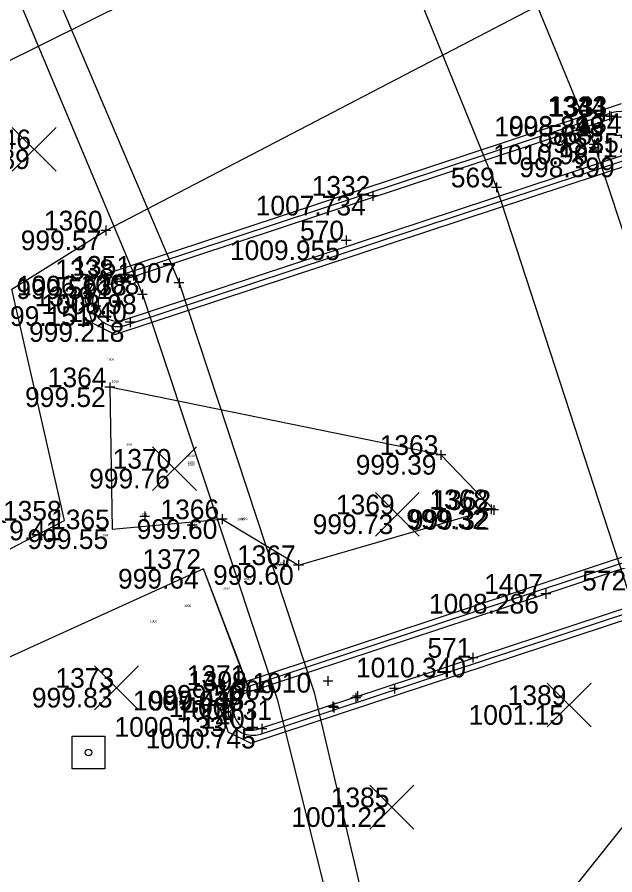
# Model space of a CAD drawing. Extents: x 2354693 to 2355622, y 637071 to 710080.
# Drawn here: x 2355324.2 to 2355360.6, y 709282.3 to 709334.6 of the extents above; entities that cross this region are included whole.
import ezdxf

# ---------------------------------------------------------------- set-up
doc = ezdxf.new("R2010")
doc.units = 0
for name, color, linetype in [('BR_X_Sub_Foot_Object', 7, 'Continuous'), ('BR_X_SV_Beam_Seat', 7, 'Continuous'), ('BR_X_SV_Pier', 7, 'Continuous'), ('BR_X_SV_Pier_Text', 7, 'Continuous'), ('DT_X_Spot_Elev', 7, 'Continuous'), ('HY_X_Water_Edge', 7, 'Continuous'), ('PM_X_Surveyed_Line', 7, 'Continuous'), ('PV_X_EOP', 7, 'Continuous'), ('SV_X_Control_Cells_Found', 7, 'Continuous'), ('SV_X_Random_Point', 7, 'Continuous'), ('SV_X_Shot_Marker', 7, 'Continuous'), ('SV_X_Text_Elevation', 7, 'Continuous'), ('SV_X_Text_Name', 7, 'Continuous'), ('SV_X_Toe_of_Slope', 7, 'Continuous')]:
    doc.layers.add(name, color=color, linetype=linetype)

msp = doc.modelspace()

# ---------------------------------------------------------------- linework, layer by layer
at = {"layer": 'BR_X_Sub_Foot_Object'}
for p, q in [((2355328.996, 709318.714), (2355360.982, 709329.286)), ((2355330.146, 709315.233), (2355362.132, 709325.804)), ((2355328.996, 709318.714), (2355328.314, 709317.359)), ((2355328.314, 709317.359), (2355328.791, 709315.915)), ((2355330.146, 709315.233), (2355328.791, 709315.915)), ((2355337.246, 709293.829), (2355369.232, 709304.4)), ((2355338.397, 709290.347), (2355370.383, 709300.918)), ((2355337.246, 709293.829), (2355336.564, 709292.473)), ((2355336.564, 709292.473), (2355337.042, 709291.029)), ((2355338.397, 709290.347), (2355337.042, 709291.029))]:
    msp.add_line(p, q, dxfattribs=at)
at = {"layer": 'BR_X_SV_Beam_Seat'}
for p, q in [((2355360.639, 709328.496), (2355360.039, 709328.496)), ((2355360.339, 709328.796), (2355360.339, 709328.196)), ((2355345.85, 709323.978), (2355345.85, 709323.378)), ((2355346.15, 709323.678), (2355345.55, 709323.678)), ((2355331.289, 709319.11), (2355331.289, 709318.51)), ((2355331.589, 709318.81), (2355330.989, 709318.81)), ((2355356.366, 709299.742), (2355356.366, 709299.142)), ((2355356.666, 709299.442), (2355356.066, 709299.442)), ((2355338.656, 709293.543), (2355338.056, 709293.543)), ((2355338.356, 709293.843), (2355338.356, 709293.243))]:
    msp.add_line(p, q, dxfattribs=at)
at = {"layer": 'BR_X_SV_Pier'}
for p, q in [((2355329.927, 709318.32), (2355360.469, 709328.414)), ((2355329.991, 709318.692), (2355360.276, 709328.701)), ((2355330.659, 709316.105), (2355361.201, 709326.199)), ((2355330.764, 709315.788), (2355361.306, 709325.882)), ((2355338.178, 709293.434), (2355368.719, 709303.528)), ((2355338.241, 709293.806), (2355368.526, 709303.816)), ((2355338.91, 709291.219), (2355369.452, 709301.313)), ((2355339.014, 709290.902), (2355369.556, 709300.996))]:
    msp.add_line(p, q, dxfattribs=at)
for centre, radius, start, end in [((2355360.835, 709327.306), 1.5, 288.2885, 108.2885), ((2355360.835, 709327.306), 1.167, 288.2885, 108.2885), ((2355330.293, 709317.212), 1.5, 108.2885, 288.2885), ((2355330.293, 709317.212), 1.167, 108.2885, 288.2885), ((2355338.544, 709292.327), 1.5, 108.2885, 288.2885), ((2355338.544, 709292.327), 1.167, 108.2885, 288.2885)]:
    msp.add_arc(centre, radius, start, end, dxfattribs=at)
at = {"layer": 'BR_X_SV_Pier_Text'}
for p, q in [((2355360.537, 709328.523), (2355359.937, 709328.523)), ((2355360.554, 709328.532), (2355359.954, 709328.532)), ((2355360.554, 709328.532), (2355359.954, 709328.532)), ((2355360.237, 709328.823), (2355360.237, 709328.223)), ((2355360.254, 709328.832), (2355360.254, 709328.232)), ((2355360.254, 709328.832), (2355360.254, 709328.232)), ((2355330.578, 709318.594), (2355329.978, 709318.594)), ((2355330.278, 709318.894), (2355330.278, 709318.294)), ((2355329.298, 709316.954), (2355328.698, 709316.954)), ((2355328.998, 709317.254), (2355328.998, 709316.654)), ((2355331.376, 709315.986), (2355330.776, 709315.986)), ((2355331.076, 709316.286), (2355331.076, 709315.686)), ((2355338.641, 709293.54), (2355338.041, 709293.54)), ((2355338.341, 709293.84), (2355338.341, 709293.24)), ((2355337.493, 709291.942), (2355336.893, 709291.942)), ((2355337.193, 709292.242), (2355337.193, 709291.642)), ((2355339.096, 709291.529), (2355339.096, 709290.929)), ((2355339.396, 709291.229), (2355338.796, 709291.229))]:
    msp.add_line(p, q, dxfattribs=at)
at = {"layer": 'HY_X_Water_Edge'}
for points in [[(2355359.12, 709336.962), (2355357.913, 709341.692), (2355351.852, 709345.867), (2355323.23, 709331.642), (2355296.554, 709310.152), (2355279.902, 709286.977), (2355296.129, 709295.23), (2355310.102, 709295.061), (2355327.095, 709303.904), (2355323.879, 709317.989), (2355329.602, 709321.567), (2355359.12, 709336.962)], [(2355353.201, 709304.549), (2355349.979, 709307.9), (2355329.846, 709312.02), (2355329.99, 709303.375), (2355336.68, 709303.987), (2355341.325, 709301.193), (2355353.039, 709304.591)], [(2355338.241, 709293.806), (2355335.553, 709300.961), (2355309.837, 709289.282), (2355293.059, 709285.327), (2355275.057, 709268.764), (2355271.816, 709252.103), (2355293.45, 709267.257), (2355309.044, 709270.656), (2355323.015, 709269.316), (2355355.379, 709278.139), (2355366.295, 709291.81), (2355368.889, 709301.061)]]:
    msp.add_lwpolyline(points, dxfattribs=at)
at = {"layer": 'PM_X_Surveyed_Line'}
for points in [[(2355180.148, 709561.237), (2355214.753, 709522.888), (2355249.307, 709484.271), (2355284.017, 709443.142), (2355315.552, 709399.77), (2355328.888, 709377.573), (2355342.967, 709349.789), (2355353.365, 709324.191), (2355361.351, 709299.648), (2355367.764, 709272.473), (2355372.191, 709243.487), (2355373.87, 709217.884), (2355371.213, 709164.414), (2355367.135, 709139.625), (2355360.061, 709111.877), (2355351.618, 709085.78), (2355342.505, 709062.338), (2355329.445, 709031.419), (2355320.624, 709012.583)], [(2355165.86, 709547.265), (2355199.549, 709510.037), (2355233.994, 709470.593), (2355267.54, 709430.367), (2355282.605, 709410.565), (2355297.684, 709388.575), (2355309.404, 709369.446), (2355323.831, 709342.426), (2355334.056, 709318.38), (2355342.286, 709293.43), (2355348.466, 709267.168), (2355351.872, 709240.375), (2355352.964, 709217.38), (2355352.456, 709191.088), (2355350.186, 709167.624), (2355345.964, 709144.005), (2355339.847, 709117.861), (2355332.105, 709093.739), (2355322.597, 709069.077), (2355314.612, 709050.664), (2355300.362, 709021.696)]]:
    msp.add_lwpolyline(points, dxfattribs=at)
at = {"layer": 'PV_X_EOP'}
for points in [[(2355180.814, 709561.741), (2355215.64, 709523.556), (2355249.922, 709484.356), (2355284.407, 709443.36), (2355315.939, 709399.966), (2355329.751, 709378.355), (2355343.524, 709350.098), (2355349.219, 709351.4), (2355359.304, 709326.795), (2355367.588, 709301.754), (2355374.108, 709275.907), (2355368.17, 709272.694), (2355372.498, 709243.563), (2355374.502, 709217.665), (2355371.414, 709164.432), (2355367.842, 709139.325), (2355361.02, 709111.642), (2355352.388, 709085.56), (2355343.445, 709061.967), (2355330.49, 709031.083), (2355321.141, 709011.801)], [(2355165.324, 709546.951), (2355198.995, 709509.502), (2355233.405, 709470.111), (2355266.728, 709429.76), (2355281.934, 709410.085), (2355297.047, 709388.167), (2355308.637, 709369.042), (2355321.448, 709342.933), (2355321.339, 709342.62), (2355331.824, 709317.677), (2355340.036, 709292.971), (2355346.601, 709266.722), (2355349.963, 709239.902), (2355351.76, 709217.379), (2355351.561, 709190.756), (2355349.316, 709167.656), (2355345.615, 709144.125), (2355339.519, 709118.013), (2355331.95, 709093.674), (2355322.309, 709069.242), (2355314.268, 709051.111), (2355300.286, 709022.246)]]:
    msp.add_lwpolyline(points, dxfattribs=at)
at = {"layer": 'SV_X_Control_Cells_Found'}
msp.add_lwpolyline([(2355327.554, 709290.772), (2355329.534, 709290.772), (2355329.534, 709288.79), (2355327.554, 709288.79), (2355327.554, 709290.772)], dxfattribs=at)
msp.add_circle((2355328.544, 709289.78), 0.2, dxfattribs=at)
at = {"layer": 'SV_X_Random_Point'}
for p, q in [((2355323.904, 709325.172), (2355326.57, 709327.842)), ((2355323.904, 709327.842), (2355326.57, 709325.172)), ((2355332.445, 709305.728), (2355335.112, 709308.398)), ((2355332.445, 709308.398), (2355335.112, 709305.728)), ((2355346.004, 709302.948), (2355348.671, 709305.618)), ((2355346.004, 709305.618), (2355348.671, 709302.948)), ((2355328.918, 709292.39), (2355331.584, 709295.06)), ((2355328.918, 709295.06), (2355331.584, 709292.39)), ((2355356.455, 709291.338), (2355359.121, 709294.008)), ((2355356.455, 709294.008), (2355359.121, 709291.338)), ((2355345.671, 709285.118), (2355348.338, 709287.788)), ((2355345.671, 709287.788), (2355348.338, 709285.118))]:
    msp.add_line(p, q, dxfattribs=at)
at = {"layer": 'SV_X_Shot_Marker'}
for p, q in [((2355359.3, 709326.897), (2355359.3, 709326.297)), ((2355359.304, 709327.095), (2355359.304, 709326.495)), ((2355361.152, 709327.356), (2355360.552, 709327.356)), ((2355359.6, 709326.597), (2355359, 709326.597)), ((2355359.604, 709326.795), (2355359.004, 709326.795)), ((2355353.365, 709324.491), (2355353.365, 709323.891)), ((2355353.665, 709324.191), (2355353.065, 709324.191)), ((2355329.602, 709321.867), (2355329.602, 709321.267)), ((2355329.902, 709321.567), (2355329.302, 709321.567)), ((2355344.223, 709321.261), (2355344.223, 709320.661)), ((2355344.522, 709320.961), (2355343.923, 709320.961)), ((2355334.056, 709318.68), (2355334.056, 709318.08)), ((2355331.824, 709317.977), (2355331.824, 709317.377)), ((2355334.356, 709318.38), (2355333.756, 709318.38)), ((2355330.301, 709317.562), (2355330.301, 709316.962)), ((2355330.332, 709317.484), (2355330.332, 709316.884)), ((2355332.124, 709317.677), (2355331.524, 709317.677)), ((2355330.601, 709317.262), (2355330.001, 709317.262)), ((2355330.632, 709317.184), (2355330.032, 709317.184)), ((2355329.846, 709312.32), (2355329.846, 709311.72)), ((2355330.146, 709312.02), (2355329.546, 709312.02)), ((2355349.979, 709308.2), (2355349.979, 709307.6)), ((2355350.279, 709307.9), (2355349.679, 709307.9)), ((2355331.964, 709304.448), (2355331.964, 709303.848)), ((2355353.339, 709304.591), (2355352.74, 709304.591)), ((2355353.501, 709304.549), (2355352.901, 709304.549)), ((2355353.039, 709304.891), (2355353.039, 709304.291)), ((2355353.201, 709304.85), (2355353.201, 709304.249)), ((2355332.264, 709304.148), (2355331.664, 709304.148)), ((2355334.858, 709303.919), (2355334.858, 709303.319)), ((2355336.98, 709303.987), (2355336.38, 709303.987)), ((2355336.68, 709304.287), (2355336.68, 709303.687)), ((2355335.158, 709303.619), (2355334.558, 709303.619)), ((2355340.422, 709301.506), (2355340.422, 709300.906)), ((2355341.325, 709301.493), (2355341.325, 709300.893)), ((2355340.722, 709301.206), (2355340.122, 709301.206)), ((2355341.625, 709301.193), (2355341.025, 709301.193)), ((2355352.239, 709295.555), (2355351.639, 709295.555)), ((2355351.939, 709295.855), (2355351.939, 709295.255)), ((2355343.416, 709294.137), (2355342.816, 709294.137)), ((2355343.116, 709294.437), (2355343.116, 709293.837)), ((2355347.155, 709293.974), (2355347.155, 709293.374)), ((2355344.904, 709293.515), (2355344.904, 709292.915)), ((2355347.455, 709293.674), (2355346.855, 709293.674)), ((2355345.114, 709293.121), (2355344.514, 709293.121)), ((2355345.204, 709293.215), (2355344.604, 709293.215)), ((2355344.814, 709293.421), (2355344.814, 709292.821)), ((2355343.71, 709292.584), (2355343.11, 709292.584)), ((2355343.777, 709292.521), (2355343.177, 709292.521)), ((2355343.41, 709292.884), (2355343.41, 709292.284)), ((2355343.477, 709292.821), (2355343.477, 709292.221))]:
    msp.add_line(p, q, dxfattribs=at)
at = {"layer": 'SV_X_Toe_of_Slope'}
for points in [[(2355359.12, 709336.962), (2355357.913, 709341.692), (2355351.852, 709345.867), (2355323.23, 709331.642), (2355296.554, 709310.152), (2355279.902, 709286.977), (2355296.129, 709295.23), (2355310.102, 709295.061), (2355327.095, 709303.904), (2355323.879, 709317.989), (2355329.602, 709321.567), (2355359.12, 709336.962)], [(2355353.201, 709304.549), (2355349.979, 709307.9), (2355329.846, 709312.02), (2355329.99, 709303.375), (2355336.68, 709303.987), (2355341.325, 709301.193), (2355353.039, 709304.591)], [(2355338.248, 709293.892), (2355335.553, 709300.961), (2355309.837, 709289.282), (2355293.059, 709285.327), (2355275.057, 709268.764), (2355271.816, 709252.103), (2355293.45, 709267.257), (2355309.044, 709270.656), (2355323.015, 709269.316), (2355355.379, 709278.139), (2355366.295, 709291.81), (2355368.889, 709301.061)]]:
    msp.add_lwpolyline(points, dxfattribs=at)

# ---------------------------------------------------------------- texts
at = {"layer": 'BR_X_SV_Beam_Seat'}
for s, p in [('1331', (2355356.611, 709328.496)), ('1008.818', (2355353.235, 709327.296)), ('1332', (2355342.124, 709323.678)), ('1007.734', (2355338.722, 709322.478)), ('1351', (2355327.561, 709318.81)), ('1006.538', (2355324.185, 709317.61)), ('1407', (2355352.622, 709299.442)), ('1008.286', (2355349.258, 709298.242)), ('1408', (2355334.602, 709293.543)), ('1007.048', (2355331.251, 709292.343))]:
    msp.add_text(s, height=1.2, dxfattribs=at).set_placement(p)
at = {"layer": 'BR_X_SV_Pier_Text'}
for s, p in [('1344', (2355356.478, 709328.532)), ('1333', (2355356.521, 709328.523)), ('1343', (2355356.538, 709328.532)), ('998.349', (2355354.126, 709327.332)), ('998.349', (2355354.126, 709327.332)), ('998.393', (2355354.128, 709327.323)), ('1342', (2355358.297, 709327.496)), ('998.352', (2355355.903, 709326.296)), ('1341', (2355357.16, 709326.009)), ('998.399', (2355354.76, 709324.809)), ('1338', (2355326.525, 709318.594)), ('999.591', (2355324.156, 709317.394)), ('1339', (2355325.263, 709316.954)), ('999.151', (2355322.876, 709315.754)), ('1340', (2355327.31, 709315.986)), ('999.218', (2355324.929, 709314.786)), ('1399', (2355334.606, 709293.54)), ('999.435', (2355332.227, 709292.34)), ('1400', (2355333.427, 709291.942)), ('1401', (2355335.368, 709291.229)), ('1000.133', (2355330.126, 709290.742)), ('1000.745', (2355332.025, 709290.029))]:
    msp.add_text(s, height=1.2, dxfattribs=at).set_placement(p)
at = {"layer": 'DT_X_Spot_Elev'}
for s, p in [('1000', (2355329.674, 709313.633)), ('1000', (2355329.965, 709312.308)), ('999', (2355330.86, 709308.462)), ('1000', (2355334.569, 709307.782)), ('1000', (2355334.574, 709307.375)), ('1000', (2355334.575, 709307.243)), ('999', (2355331.794, 709304.208)), ('1000', (2355337.603, 709303.917)), ('1000', (2355337.784, 709303.938)), ('1000', (2355334.621, 709303.569)), ('999', (2355329.422, 709302.94)), ('1000', (2355340.053, 709301.225)), ('1000', (2355339.809, 709301.115)), ('1000', (2355337.967, 709300.278)), ('1000', (2355336.712, 709299.708)), ('1000', (2355334.365, 709298.642)), ('1000', (2355332.286, 709297.698))]:
    msp.add_text(s, height=0.14, rotation=360, dxfattribs=at).set_placement(p)
at = {"layer": 'SV_X_Text_Elevation'}
for s, p in [('999.89', (2355320.066, 709325.307)), ('1010.98', (2355353.158, 709325.595)), ('999.57', (2355324.422, 709320.367)), ('1009.955', (2355337.151, 709319.761)), ('1008.98', (2355325.678, 709316.477)), ('999.52', (2355324.685, 709310.82)), ('999.39', (2355344.808, 709306.7)), ('999.76', (2355328.586, 709305.863)), ('999.32', (2355347.878, 709303.391)), ('999.32', (2355348.039, 709303.35)), ('999.41', (2355321.932, 709302.704)), ('999.60', (2355331.479, 709302.787)), ('999.73', (2355342.186, 709303.083)), ('999.55', (2355324.834, 709302.175)), ('999.64', (2355330.341, 709299.761)), ('999.60', (2355336.124, 709299.993)), ('1010.340', (2355344.822, 709294.355)), ('999.83', (2355325.099, 709292.525)), ('999.50', (2355333.046, 709292.692)), ('1009.31', (2355333.914, 709291.771)), ('1001.15', (2355351.674, 709291.473)), ('1001.22', (2355340.885, 709285.253))]:
    msp.add_text(s, height=1.2, dxfattribs=at).set_placement(p)
at = {"layer": 'SV_X_Text_Name'}
for s, p in [('568', (2355356.509, 709326.795)), ('1346', (2355321.48, 709326.507)), ('569', (2355350.588, 709324.191)), ('1360', (2355325.836, 709321.567)), ('570', (2355341.415, 709320.961)), ('1007', (2355330.312, 709318.38)), ('1008', (2355328.071, 709317.677)), ('1364', (2355326.069, 709312.02)), ('1363', (2355346.263, 709307.9)), ('1370', (2355330.013, 709307.063)), ('1369', (2355343.602, 709304.283)), ('1368', (2355349.286, 709304.591)), ('1362', (2355349.475, 709304.549)), ('1358', (2355323.342, 709303.904)), ('1366', (2355332.924, 709303.987)), ('1365', (2355326.27, 709303.375)), ('1367', (2355337.581, 709301.193)), ('1372', (2355331.827, 709300.961)), ('572', (2355358.583, 709299.648)), ('571', (2355349.168, 709295.555)), ('1371', (2355334.519, 709293.892)), ('1373', (2355326.535, 709293.725)), ('1010', (2355338.521, 709293.43)), ('1009', (2355336.301, 709292.971)), ('1389', (2355354.053, 709292.673)), ('1385', (2355343.284, 709286.453))]:
    msp.add_text(s, height=1.2, dxfattribs=at).set_placement(p)

doc.saveas('drawing.dxf')
